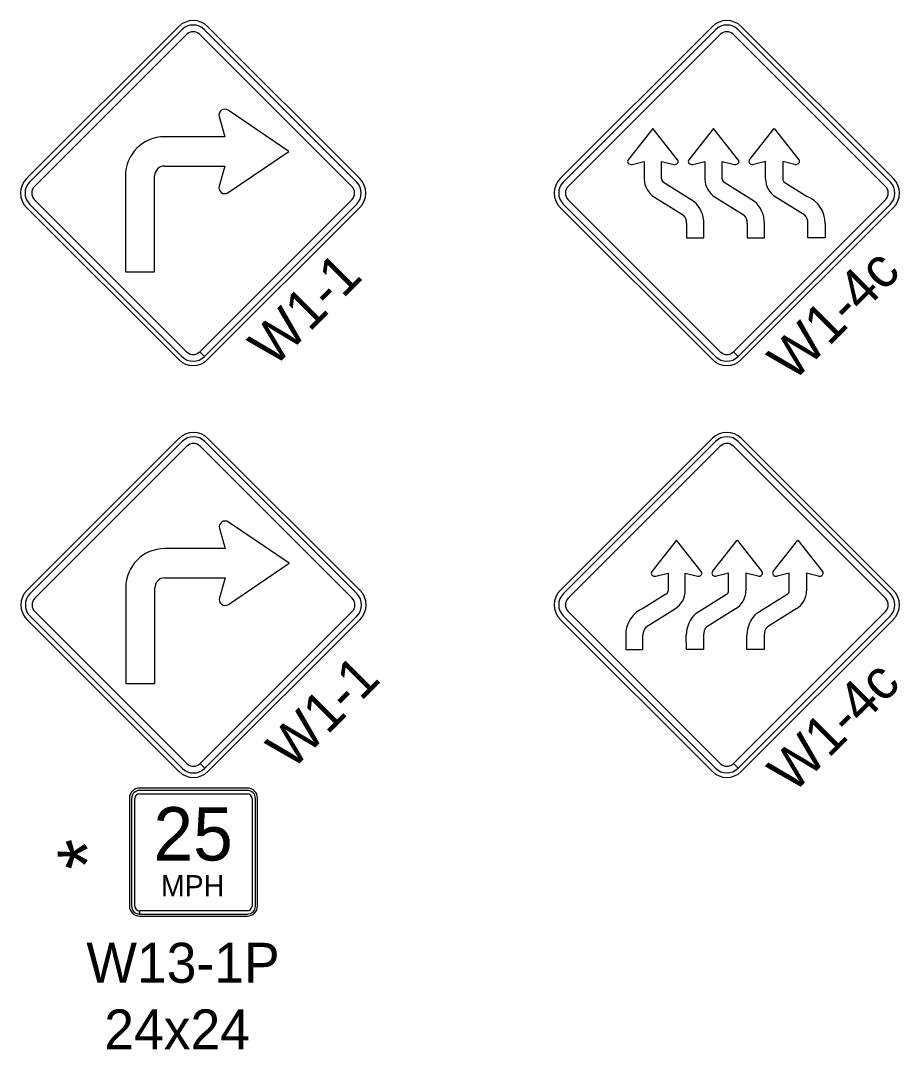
# Model space of a CAD drawing. Extents: x 1458 to 4498, y 17709 to 24109.
# Drawn here: x 2114 to 2443.3, y 23241.5 to 23627.2 of the extents above; entities that cross this region are included whole.
import ezdxf

# ---------------------------------------------------------------- set-up
doc = ezdxf.new("R2010")
doc.units = 0
doc.layers.add('P_TRAF_TCP_General', color=7, linetype='Continuous')

msp = doc.modelspace()

# ---------------------------------------------------------------- linework, layer by layer
at = {"layer": 'P_TRAF_TCP_General'}
for p, q in [((2173.24, 23624.96), (2116.24, 23567.95)), ((2174.43, 23623.78), (2117.42, 23566.77)), ((2174.43, 23623.78), (2117.42, 23566.77)), ((2239.91, 23566.77), (2182.91, 23623.78)), ((2239.91, 23566.77), (2182.91, 23623.78)), ((2241.1, 23567.95), (2184.09, 23624.96)), ((2373.24, 23624.96), (2316.24, 23567.95)), ((2374.43, 23623.78), (2317.42, 23566.77)), ((2374.43, 23623.78), (2317.42, 23566.77)), ((2439.91, 23566.77), (2382.91, 23623.78)), ((2439.91, 23566.77), (2382.91, 23623.78)), ((2441.1, 23567.95), (2384.09, 23624.96)), ((2119.19, 23565), (2176.19, 23622.01)), ((2119.19, 23565), (2176.19, 23622.01)), ((2181.14, 23622.01), (2238.15, 23565)), ((2181.14, 23622.01), (2238.15, 23565)), ((2319.19, 23565), (2376.19, 23622.01)), ((2319.19, 23565), (2376.19, 23622.01)), ((2381.14, 23622.01), (2438.15, 23565)), ((2381.14, 23622.01), (2438.15, 23565)), ((2214.56, 23578.15), (2191.76, 23593.59)), ((2188.39, 23591.21), (2190.59, 23583.64)), ((2350.97, 23586.74), (2341.71, 23575.02)), ((2360.22, 23575.02), (2350.97, 23586.74)), ((2373.69, 23586.74), (2364.44, 23575.02)), ((2382.95, 23575.02), (2373.69, 23586.74)), ((2387.17, 23575.02), (2396.42, 23586.74)), ((2396.42, 23586.74), (2405.66, 23575.05)), ((2190.59, 23583.64), (2167.91, 23583.64)), ((2191.79, 23562.73), (2214.56, 23578.15)), ((2343.17, 23573.3), (2347.71, 23574.43)), ((2347.71, 23574.43), (2347.71, 23567.8)), ((2354.17, 23567.83), (2354.17, 23574.44)), ((2354.17, 23574.44), (2358.76, 23573.3)), ((2365.9, 23573.3), (2370.44, 23574.43)), ((2370.44, 23574.43), (2370.44, 23567.8)), ((2376.9, 23567.83), (2376.9, 23574.44)), ((2376.9, 23574.44), (2381.49, 23573.3)), ((2387.17, 23575.02), (2387.17, 23575.02)), ((2393.16, 23574.43), (2388.63, 23573.3)), ((2393.16, 23567.95), (2393.16, 23574.43)), ((2404.21, 23573.3), (2399.63, 23574.44)), ((2399.63, 23574.44), (2399.63, 23567.83)), ((2167.91, 23572.66), (2190.59, 23572.66)), ((2190.59, 23572.66), (2188.42, 23565.19)), ((2153.26, 23568.99), (2153.26, 23533.04)), ((2164.24, 23533.04), (2164.24, 23568.99)), ((2366.36, 23559.42), (2354.94, 23566.56)), ((2389.09, 23559.42), (2377.67, 23566.56)), ((2400.39, 23566.56), (2408.8, 23561.31)), ((2117.42, 23558.29), (2174.43, 23501.28)), ((2117.42, 23558.29), (2174.43, 23501.28)), ((2176.19, 23503.05), (2119.19, 23560.06)), ((2238.15, 23560.06), (2181.16, 23503.07)), ((2238.15, 23560.06), (2181.16, 23503.07)), ((2182.93, 23501.3), (2239.91, 23558.29)), ((2182.93, 23501.3), (2239.91, 23558.29)), ((2317.42, 23558.29), (2374.43, 23501.28)), ((2376.19, 23503.05), (2319.19, 23560.06)), ((2351.55, 23561.05), (2362.38, 23554.29)), ((2374.28, 23561.05), (2385.11, 23554.29)), ((2438.15, 23560.06), (2381.16, 23503.07)), ((2438.15, 23560.06), (2381.16, 23503.07)), ((2382.93, 23501.3), (2439.91, 23558.29)), ((2382.93, 23501.3), (2439.91, 23558.29)), ((2407.84, 23554.29), (2396.84, 23561.16)), ((2116.24, 23557.11), (2173.24, 23500.1)), ((2184.09, 23500.1), (2241.1, 23557.11)), ((2316.24, 23557.11), (2373.24, 23500.1)), ((2384.09, 23500.1), (2441.1, 23557.11)), ((2363.58, 23551.17), (2363.57, 23545.8)), ((2370.03, 23545.79), (2370.04, 23551.13)), ((2386.3, 23551.17), (2386.3, 23545.8)), ((2392.76, 23545.79), (2392.77, 23551.13)), ((2409.02, 23545.8), (2409.03, 23551.18)), ((2415.5, 23551.15), (2415.49, 23545.79)), ((2363.57, 23545.8), (2370.03, 23545.79)), ((2386.3, 23545.8), (2392.76, 23545.79)), ((2415.49, 23545.79), (2409.02, 23545.8)), ((2153.26, 23533.04), (2164.24, 23533.04)), ((2182.91, 23501.28), (2181.14, 23503.05)), ((2182.91, 23501.28), (2181.14, 23503.05)), ((2181.16, 23503.07), (2182.93, 23501.3)), ((2181.16, 23503.07), (2182.93, 23501.3)), ((2382.91, 23501.28), (2381.14, 23503.05)), ((2382.91, 23501.28), (2381.14, 23503.05)), ((2381.16, 23503.07), (2382.93, 23501.3)), ((2381.16, 23503.07), (2382.93, 23501.3)), ((2173.36, 23470.59), (2116.36, 23413.58)), ((2174.54, 23469.41), (2117.54, 23412.4)), ((2240.03, 23412.4), (2183.03, 23469.41)), ((2241.22, 23413.58), (2184.21, 23470.59)), ((2373.24, 23470.61), (2316.24, 23413.6)), ((2374.43, 23469.42), (2317.42, 23412.42)), ((2374.43, 23469.42), (2317.42, 23412.42)), ((2439.91, 23412.42), (2382.91, 23469.42)), ((2439.91, 23412.42), (2382.91, 23469.42)), ((2441.1, 23413.6), (2384.09, 23470.61)), ((2119.31, 23410.63), (2176.31, 23467.64)), ((2181.26, 23467.64), (2238.26, 23410.63)), ((2319.19, 23410.65), (2376.19, 23467.65)), ((2319.19, 23410.65), (2376.19, 23467.65)), ((2381.14, 23467.65), (2438.15, 23410.65)), ((2381.14, 23467.65), (2438.15, 23410.65)), ((2214.68, 23423.78), (2191.87, 23439.22)), ((2188.51, 23436.84), (2190.7, 23429.27)), ((2359.83, 23432.38), (2350.59, 23420.69)), ((2369.08, 23420.67), (2359.83, 23432.38)), ((2373.3, 23420.67), (2382.56, 23432.38)), ((2382.56, 23432.38), (2391.81, 23420.67)), ((2396.03, 23420.67), (2405.28, 23432.38)), ((2405.28, 23432.38), (2414.54, 23420.67)), ((2190.7, 23429.27), (2168.03, 23429.27)), ((2191.91, 23408.36), (2214.68, 23423.78)), ((2352.04, 23418.95), (2356.62, 23420.09)), ((2356.62, 23420.09), (2356.62, 23413.47)), ((2363.09, 23413.59), (2363.09, 23420.08)), ((2363.09, 23420.08), (2367.62, 23418.95)), ((2369.09, 23420.67), (2369.08, 23420.67)), ((2379.35, 23420.09), (2374.77, 23418.95)), ((2379.35, 23413.48), (2379.35, 23420.09)), ((2390.35, 23418.95), (2385.82, 23420.08)), ((2385.82, 23420.08), (2385.82, 23413.45)), ((2402.08, 23420.09), (2397.49, 23418.95)), ((2402.08, 23413.48), (2402.08, 23420.09)), ((2413.08, 23418.95), (2408.54, 23420.08)), ((2408.54, 23420.08), (2408.54, 23413.45)), ((2168.03, 23418.29), (2190.7, 23418.29)), ((2190.7, 23418.29), (2188.54, 23410.82)), ((2153.38, 23414.62), (2153.38, 23378.67)), ((2164.36, 23378.67), (2164.36, 23414.62)), ((2355.86, 23412.21), (2347.46, 23406.95)), ((2367.16, 23405.07), (2378.59, 23412.21)), ((2389.89, 23405.07), (2401.31, 23412.21)), ((2117.54, 23403.92), (2174.54, 23346.91)), ((2176.31, 23348.68), (2119.31, 23405.69)), ((2238.26, 23405.69), (2181.28, 23348.7)), ((2183.04, 23346.93), (2240.03, 23403.92)), ((2317.42, 23403.93), (2374.43, 23346.93)), ((2376.19, 23348.7), (2319.19, 23405.7)), ((2348.42, 23399.93), (2359.41, 23406.8)), ((2381.97, 23406.7), (2371.14, 23399.93)), ((2438.15, 23405.7), (2381.16, 23348.71)), ((2438.15, 23405.7), (2381.16, 23348.71)), ((2382.93, 23346.95), (2439.91, 23403.93)), ((2382.93, 23346.95), (2439.91, 23403.93)), ((2404.7, 23406.7), (2393.87, 23399.93)), ((2116.36, 23402.74), (2173.36, 23345.73)), ((2184.21, 23345.73), (2241.22, 23402.74)), ((2316.24, 23402.75), (2373.24, 23345.75)), ((2384.09, 23345.75), (2441.1, 23402.75)), ((2340.76, 23396.79), (2340.76, 23391.43)), ((2347.23, 23391.44), (2347.22, 23396.82)), ((2363.49, 23391.43), (2363.48, 23396.77)), ((2369.95, 23396.81), (2369.96, 23391.44)), ((2386.22, 23391.43), (2386.21, 23396.77)), ((2392.68, 23396.81), (2392.68, 23391.44)), ((2340.76, 23391.43), (2347.23, 23391.44)), ((2369.96, 23391.44), (2363.49, 23391.43)), ((2392.68, 23391.44), (2386.22, 23391.43)), ((2153.38, 23378.67), (2164.36, 23378.67)), ((2183.03, 23346.91), (2181.26, 23348.68)), ((2183.03, 23346.91), (2181.26, 23348.68)), ((2181.28, 23348.7), (2183.04, 23346.93)), ((2181.28, 23348.7), (2183.04, 23346.93)), ((2382.91, 23346.93), (2381.14, 23348.7)), ((2382.91, 23346.93), (2381.14, 23348.7)), ((2381.16, 23348.71), (2382.93, 23346.95)), ((2381.16, 23348.71), (2382.93, 23346.95)), ((2198.98, 23339.48), (2158.59, 23339.48)), ((2198.98, 23338.63), (2158.59, 23338.63)), ((2198.98, 23338.63), (2158.59, 23338.63)), ((2154.79, 23335.69), (2154.79, 23295.3)), ((2155.59, 23335.63), (2155.59, 23295.24)), ((2155.59, 23335.63), (2155.59, 23295.24)), ((2156.84, 23295.24), (2156.84, 23335.63)), ((2158.59, 23337.38), (2198.98, 23337.38)), ((2200.73, 23335.63), (2200.73, 23295.24)), ((2201.98, 23295.24), (2201.98, 23335.63)), ((2201.98, 23295.24), (2201.98, 23335.63)), ((2202.78, 23295.3), (2202.78, 23335.69)), ((2158.59, 23292.25), (2158.59, 23293.49)), ((2158.59, 23292.25), (2198.98, 23292.25)), ((2158.59, 23291.5), (2198.98, 23291.5)), ((2198.98, 23293.49), (2158.61, 23293.49)), ((2158.61, 23293.49), (2158.61, 23292.25)), ((2158.61, 23292.25), (2198.98, 23292.25))]:
    msp.add_line(p, q, dxfattribs=at)
for centre, radius, start, end in [((2178.67, 23619.54), 7.67, 45, 135), ((2378.67, 23619.54), 7.67, 45, 135), ((2178.67, 23619.54), 6, 45, 135), ((2178.67, 23619.54), 6, 45, 135), ((2378.67, 23619.54), 6, 45, 135), ((2378.67, 23619.54), 6, 45, 135), ((2178.67, 23619.54), 3.5, 45, 135), ((2178.67, 23619.54), 3.5, 45, 135), ((2378.67, 23619.54), 3.5, 45, 135), ((2378.67, 23619.54), 3.5, 45, 135), ((2190.52, 23591.77), 2.2, 55.8866, 194.6737), ((2167.91, 23568.99), 14.65, 90, 180), ((2167.91, 23568.99), 3.67, 90, 180), ((2121.66, 23562.53), 7.67, 135, 225), ((2121.66, 23562.53), 6, 135, 225), ((2121.66, 23562.53), 6, 135, 225), ((2235.67, 23562.53), 6, 315, 45), ((2235.67, 23562.53), 6, 315, 45), ((2235.67, 23562.53), 7.67, 315, 45), ((2321.66, 23562.53), 7.67, 135, 225), ((2321.66, 23562.53), 6, 135, 225), ((2321.66, 23562.53), 6, 135, 225), ((2355.71, 23567.89), 8, 180.6628, 238.6922), ((2355.71, 23567.89), 1.54, 182.2287, 239.8806), ((2378.44, 23567.89), 8, 180.6628, 238.6922), ((2378.44, 23567.89), 1.54, 182.2287, 239.8806), ((2401.17, 23567.89), 8, 179.6179, 237.2958), ((2401.17, 23567.89), 1.54, 182.4295, 239.8797), ((2435.67, 23562.53), 6, 315, 45), ((2435.67, 23562.53), 6, 315, 45), ((2435.67, 23562.53), 7.67, 315, 45), ((2121.66, 23562.53), 3.5, 135, 225), ((2121.66, 23562.53), 3.5, 135, 225), ((2190.52, 23564.53), 2.2, 162.5373, 305.227), ((2235.67, 23562.53), 3.5, 315, 45), ((2235.67, 23562.53), 3.5, 315, 45), ((2321.66, 23562.53), 3.5, 135, 225), ((2321.66, 23562.53), 3.5, 135, 225), ((2435.67, 23562.53), 3.5, 315, 45), ((2435.67, 23562.53), 3.5, 315, 45), ((2359.16, 23551.26), 10.88, 359.2809, 48.5613), ((2381.89, 23551.26), 10.88, 359.2809, 48.5613), ((2404.62, 23551.26), 10.88, 359.3947, 67.4081), ((2359.23, 23551.29), 4.35, 358.3973, 43.563), ((2381.96, 23551.29), 4.35, 358.3973, 43.563), ((2404.69, 23551.29), 4.35, 358.5119, 43.5629), ((2178.67, 23505.52), 7.67, 225, 315), ((2178.67, 23505.52), 6, 225, 315), ((2178.67, 23505.52), 6, 225, 315), ((2178.67, 23505.52), 3.5, 225, 315), ((2178.67, 23505.52), 3.5, 225, 315), ((2378.67, 23505.52), 7.67, 225, 315), ((2378.67, 23505.52), 6, 225, 315), ((2378.67, 23505.52), 6, 225, 315), ((2378.67, 23505.52), 3.5, 225, 315), ((2378.67, 23505.52), 3.5, 225, 315), ((2178.79, 23465.17), 7.67, 45, 135), ((2378.67, 23465.18), 7.67, 45, 135), ((2178.79, 23465.17), 6, 45, 135), ((2378.67, 23465.18), 6, 45, 135), ((2378.67, 23465.18), 6, 45, 135), ((2178.79, 23465.17), 3.5, 45, 135), ((2378.67, 23465.18), 3.5, 45, 135), ((2378.67, 23465.18), 3.5, 45, 135), ((2190.64, 23437.4), 2.2, 55.8866, 194.6737), ((2168.03, 23414.62), 14.65, 90, 180), ((2168.03, 23414.62), 3.67, 90, 180), ((2121.78, 23408.16), 7.67, 135, 225), ((2121.78, 23408.16), 6, 135, 225), ((2235.79, 23408.16), 6, 315, 45), ((2235.79, 23408.16), 7.67, 315, 45), ((2321.66, 23408.18), 7.67, 135, 225), ((2321.66, 23408.18), 6, 135, 225), ((2321.66, 23408.18), 6, 135, 225), ((2355.09, 23413.54), 1.54, 300.1203, 357.5705), ((2355.09, 23413.54), 8, 302.7042, 0.3821), ((2377.81, 23413.54), 1.54, 300.1194, 357.7713), ((2377.81, 23413.54), 8, 301.3078, 359.3372), ((2400.54, 23413.54), 1.54, 300.1194, 357.7713), ((2400.54, 23413.54), 8, 301.3078, 359.3372), ((2435.67, 23408.18), 6, 315, 45), ((2435.67, 23408.18), 6, 315, 45), ((2435.67, 23408.18), 7.67, 315, 45), ((2121.78, 23408.16), 3.5, 135, 225), ((2190.64, 23410.16), 2.2, 162.5373, 305.227), ((2235.79, 23408.16), 3.5, 315, 45), ((2321.66, 23408.18), 3.5, 135, 225), ((2321.66, 23408.18), 3.5, 135, 225), ((2435.67, 23408.18), 3.5, 315, 45), ((2435.67, 23408.18), 3.5, 315, 45), ((2351.64, 23396.91), 10.88, 112.5919, 180.6053), ((2374.36, 23396.91), 10.88, 131.4387, 180.7191), ((2397.09, 23396.91), 10.88, 131.4387, 180.7191), ((2351.57, 23396.94), 4.35, 136.4371, 181.4881), ((2374.29, 23396.94), 4.35, 136.437, 181.6027), ((2397.02, 23396.94), 4.35, 136.437, 181.6027), ((2178.79, 23351.15), 7.67, 225, 315), ((2178.79, 23351.15), 6, 225, 315), ((2178.79, 23351.15), 3.5, 225, 315), ((2378.67, 23351.17), 7.67, 225, 315), ((2378.67, 23351.17), 6, 225, 315), ((2378.67, 23351.17), 6, 225, 315), ((2378.67, 23351.17), 3.5, 225, 315), ((2378.67, 23351.17), 3.5, 225, 315), ((2158.59, 23335.69), 3.8, 90, 180), ((2158.59, 23335.63), 3, 90, 180), ((2158.59, 23335.63), 3, 90, 180), ((2198.98, 23335.69), 3.8, 0, 90), ((2198.98, 23335.63), 3, 0, 90), ((2198.98, 23335.63), 3, 0, 90), ((2158.59, 23335.63), 1.75, 90, 180), ((2198.98, 23335.63), 1.75, 0, 90), ((2158.59, 23295.3), 3.8, 180, 270), ((2198.98, 23295.3), 3.8, 270, 0), ((2158.59, 23295.24), 3, 180, 270), ((2158.59, 23295.24), 3, 180, 270), ((2158.59, 23295.24), 1.75, 180, 270), ((2198.98, 23295.24), 3, 270, 0), ((2198.98, 23295.24), 3, 270, 0), ((2198.98, 23295.24), 1.75, 270, 0)]:
    msp.add_arc(centre, radius, start, end, dxfattribs=at)
for centre, major_axis, start_param, end_param in [((2342.81, 23574.39), (1.32, 0), 2.546183, 4.994883), ((2359.13, 23574.39), (1.32, 0), 4.429945, 6.875191), ((2365.53, 23574.39), (1.32, 0), 2.546183, 4.994883), ((2381.86, 23574.39), (1.32, 0), 4.429945, 6.875191), ((2388.26, 23574.39), (1.32, 0), 2.546183, 4.994883), ((2404.58, 23574.39), (1.32, 0), 4.429945, 6.902987), ((2351.67, 23420.04), (-1.32, 0), 5.663384, 8.136425), ((2367.99, 23420.04), (-1.32, 0), 1.288302, 3.737003), ((2374.4, 23420.04), (-1.32, 0), 5.69118, 8.136425), ((2390.72, 23420.04), (-1.32, 0), 1.288302, 3.737003), ((2397.12, 23420.04), (-1.32, 0), 5.69118, 8.136425), ((2413.45, 23420.04), (-1.32, 0), 1.288302, 3.737003)]:
    msp.add_ellipse(centre, major_axis=major_axis, ratio=0.857143, start_param=start_param, end_param=end_param, dxfattribs=at)

# ---------------------------------------------------------------- texts
for s, height, rotation, p in [('W1-4c', 14.994, 45, (2403.4, 23491.38)), ('W1-1', 14.994, 45, (2208.82, 23496.8)), ('W1-1', 14.994, 45, (2215.53, 23345.84)), ('W1-4c', 14.994, 45, (2403.4, 23337.03)), ('*', 22.14, 90, (2150.01, 23308.96))]:
    msp.add_text(s, height=height, rotation=rotation, dxfattribs=at).set_placement(p)
for s, height, p in [('25', 19.992, (2163.79, 23312.34)), ('MPH', 7.997, (2166.56, 23298.85)), ('W13-1P', 14.994, (2138.67, 23266.51)), ('24x24', 14.994, (2145.34, 23241.52))]:
    msp.add_text(s, height=height, dxfattribs=at).set_placement(p)

doc.saveas('drawing.dxf')
